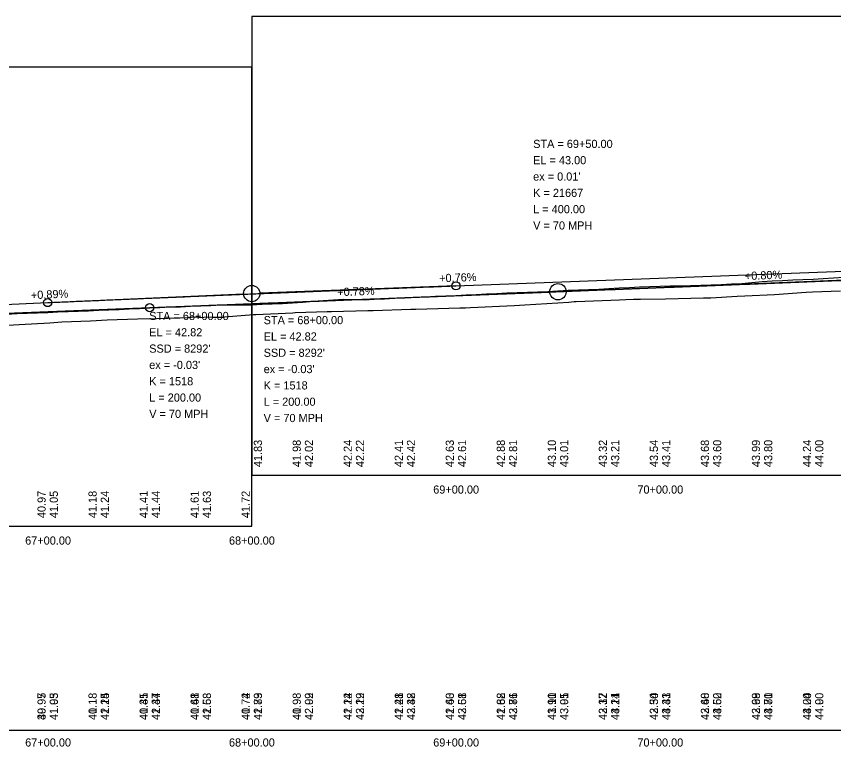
# Model space of a CAD drawing. Extents: x 3880794 to 3915434, y 287517 to 300173.
# Drawn here: x 3887223 to 3887623.4, y 297716.1 to 298074.2 of the extents above; entities that cross this region are included whole.
import ezdxf

# ---------------------------------------------------------------- set-up
doc = ezdxf.new("R2010")
doc.units = 0
for name, color, linetype in [('Level 1', 7, 'Continuous'), ('Level 2', 7, 'Continuous'), ('Level 30', 7, 'Continuous'), ('Level 31', 7, 'Continuous'), ('Level 32', 7, 'Continuous'), ('Level 62', 7, 'Continuous'), ('Level 63', 7, 'Continuous')]:
    doc.layers.add(name, color=color, linetype=linetype)

msp = doc.modelspace()

# ---------------------------------------------------------------- linework, layer by layer
at = {"layer": 'Level 1'}
for p, q in [((3887688.3, 297947.19), (3887492.29, 297939.35)), ((3887288.3, 297931.38), (3887484.3, 297939.03)), ((3886713.3, 297908.91), (3887288.3, 297931.38))]:
    msp.add_line(p, q, dxfattribs=at)
for points in [[(3887521.59, 297935.39), (3887525.37, 297935.54), (3887528.7, 297935.59), (3887541.06, 297935.71), (3887559.54, 297936.12), (3887563.11, 297936.16), (3887576.02, 297936.94), (3887579.85, 297937.17), (3887594.39, 297937.86), (3887609.96, 297938.98), (3887613.02, 297939.16), (3887626.71, 297939.64)], [(3887215.89, 297922.63), (3887224.27, 297923.17), (3887239.4, 297923.99), (3887245.2, 297924.35), (3887259.26, 297924.86), (3887267.48, 297925.36), (3887282.24, 297925.81), (3887291.65, 297925.98), (3887303.06, 297926.43), (3887307.21, 297926.6), (3887308.82, 297926.73), (3887311.81, 297926.88), (3887313.02, 297926.58), (3887314.82, 297926.78), (3887316.18, 297926.81), (3887319.27, 297926.76), (3887323.29, 297926.67), (3887324.28, 297926.76), (3887324.99, 297926.94), (3887339.06, 297927.95), (3887340.27, 297928.01), (3887358.47, 297928.9), (3887359.53, 297928.94), (3887375.16, 297929.54), (3887376.6, 297929.42), (3887376.92, 297929.41), (3887377.28, 297929.41), (3887395.12, 297929.99), (3887397.71, 297930.02), (3887416.2, 297930.69), (3887418.61, 297930.69), (3887440.14, 297931.25), (3887442.95, 297931.29), (3887445.4, 297931.37), (3887466.9, 297932.5), (3887469.46, 297932.63), (3887472.12, 297932.75), (3887493.63, 297934.09), (3887496.17, 297934.32), (3887497.14, 297934.38), (3887518.43, 297935.25), (3887521.59, 297935.39)]]:
    msp.add_lwpolyline(points, dxfattribs=at)
msp.add_circle((3887488.3, 297939.19), 4, dxfattribs=at)
msp.add_spline([(3887288.3, 297931.38), (3887296.3, 297931.69), (3887304.3, 297932), (3887312.3, 297932.31), (3887320.3, 297932.63), (3887328.3, 297932.94), (3887336.3, 297933.25), (3887344.3, 297933.57), (3887352.3, 297933.88), (3887360.3, 297934.2), (3887368.3, 297934.51), (3887376.3, 297934.82), (3887384.3, 297935.14), (3887392.3, 297935.45), (3887400.3, 297935.77), (3887408.3, 297936.08), (3887416.3, 297936.4), (3887424.3, 297936.71), (3887432.3, 297937.03), (3887440.3, 297937.34), (3887448.3, 297937.66), (3887456.3, 297937.97), (3887464.3, 297938.29), (3887472.3, 297938.6), (3887480.3, 297938.92), (3887488.3, 297939.24), (3887496.3, 297939.55), (3887504.3, 297939.87), (3887512.3, 297940.19), (3887520.3, 297940.5), (3887528.3, 297940.82), (3887536.3, 297941.14), (3887544.3, 297941.45), (3887552.3, 297941.77), (3887560.3, 297942.09), (3887568.3, 297942.41), (3887576.3, 297942.73), (3887584.3, 297943.04), (3887592.3, 297943.36), (3887600.3, 297943.68), (3887608.3, 297944), (3887616.3, 297944.32), (3887624.3, 297944.64), (3887632.3, 297944.95), (3887640.3, 297945.27), (3887648.3, 297945.59), (3887656.3, 297945.91), (3887664.3, 297946.23), (3887672.3, 297946.55), (3887680.3, 297946.87), (3887688.3, 297947.19)], degree=3, dxfattribs=at)
at = {"layer": 'Level 2'}
for p, q in [((3887438.3, 297942.07), (3888173.3, 297969.84)), ((3887438.3, 297942.07), (3887342.29, 297938.44)), ((3887238.3, 297933.85), (3887334.3, 297938.11)), ((3886763.3, 297912.78), (3887238.3, 297933.85))]:
    msp.add_line(p, q, dxfattribs=at)
for points in [[(3887538.3, 297941.91), (3887543.3, 297942.1), (3887548.3, 297942.11), (3887553.3, 297942.2), (3887558.3, 297942.37), (3887563.3, 297942.57), (3887568.3, 297942.78), (3887573.3, 297943.02), (3887578.3, 297943.21), (3887583.3, 297943.7), (3887588.3, 297944.12), (3887593.3, 297944.45), (3887598.3, 297944.71), (3887603.3, 297944.97), (3887608.3, 297945.23), (3887613.3, 297945.41), (3887618.3, 297945.67), (3887623.3, 297946), (3887628.3, 297946.33)], [(3887218.3, 297928.22), (3887223.3, 297928.42), (3887228.3, 297928.61), (3887233.3, 297928.83), (3887238.3, 297929.03), (3887243.3, 297929.24), (3887248.3, 297929.44), (3887253.3, 297929.65), (3887258.3, 297929.85), (3887263.3, 297930.07), (3887268.3, 297930.29), (3887273.3, 297930.51), (3887278.3, 297930.72), (3887283.3, 297930.97), (3887288.3, 297931.23), (3887293.3, 297931.49), (3887298.3, 297931.75), (3887303.3, 297931.83), (3887308.3, 297932.04), (3887313.3, 297932.25), (3887318.3, 297932.46), (3887323.3, 297932.67), (3887328.3, 297932.76), (3887333.3, 297932.78), (3887338.3, 297932.81), (3887343.3, 297933), (3887348.3, 297933.23), (3887353.3, 297933.46), (3887358.3, 297933.69), (3887363.3, 297934.1), (3887368.3, 297934.51), (3887373.3, 297934.92), (3887378.3, 297935.19), (3887383.3, 297935.48), (3887388.3, 297935.38), (3887393.3, 297935.14), (3887398.3, 297935.45), (3887403.3, 297935.75), (3887408.3, 297936.03), (3887413.3, 297936.25), (3887418.3, 297936.49), (3887423.3, 297936.73), (3887428.3, 297936.96), (3887433.3, 297937.19), (3887438.3, 297937.35), (3887443.3, 297937.59), (3887448.3, 297937.86), (3887453.3, 297938.13), (3887458.3, 297938.38), (3887463.3, 297938.59), (3887468.3, 297938.79), (3887473.3, 297938.99), (3887478.3, 297939.07), (3887483.3, 297939.32), (3887488.3, 297939.69), (3887493.3, 297939.88), (3887498.3, 297940.04), (3887503.3, 297940.21), (3887508.3, 297940.5), (3887513.3, 297940.81), (3887518.3, 297941.04), (3887523.3, 297941.28), (3887528.3, 297941.52), (3887533.3, 297941.71), (3887538.3, 297941.91)]]:
    msp.add_lwpolyline(points, dxfattribs=at)
for centre, radius in [((3887338.3, 297938.29), 4), ((3887438.3, 297942.07), 2), ((3887238.3, 297933.85), 2)]:
    msp.add_circle(centre, radius, dxfattribs=at)
msp.add_spline([(3887238.3, 297933.85), (3887242.3, 297934.03), (3887246.3, 297934.21), (3887250.3, 297934.38), (3887254.3, 297934.56), (3887258.3, 297934.73), (3887262.3, 297934.91), (3887266.3, 297935.08), (3887270.3, 297935.26), (3887274.3, 297935.43), (3887278.3, 297935.6), (3887282.3, 297935.77), (3887286.3, 297935.95), (3887290.3, 297936.12), (3887294.3, 297936.29), (3887298.3, 297936.46), (3887302.3, 297936.63), (3887306.3, 297936.79), (3887310.3, 297936.96), (3887314.3, 297937.13), (3887318.3, 297937.3), (3887322.3, 297937.47), (3887326.3, 297937.63), (3887330.3, 297937.8), (3887334.3, 297937.96), (3887338.3, 297938.13), (3887342.3, 297938.29), (3887346.3, 297938.45), (3887350.3, 297938.62), (3887354.3, 297938.78), (3887358.3, 297938.94), (3887362.3, 297939.1), (3887366.3, 297939.26), (3887370.3, 297939.42), (3887374.3, 297939.58), (3887378.3, 297939.74), (3887382.3, 297939.9), (3887386.3, 297940.06), (3887390.3, 297940.22), (3887394.3, 297940.37), (3887398.3, 297940.53), (3887402.3, 297940.69), (3887406.3, 297940.84), (3887410.3, 297941), (3887414.3, 297941.15), (3887418.3, 297941.31), (3887422.3, 297941.46), (3887426.3, 297941.61), (3887430.3, 297941.77), (3887434.3, 297941.92), (3887438.3, 297942.07)], degree=3, dxfattribs=at)
at = {"layer": 'Level 31'}
msp.add_circle((3887288.3, 297931.38), 2, dxfattribs=at)
at = {"layer": 'Level 62'}
for points in [[(3887338.3, 297849.19), (3888038.3, 297849.19), (3888038.3, 298074.19), (3887338.3, 298074.19)], [(3887338.3, 297849.19), (3888038.3, 297849.19), (3888038.3, 298074.19), (3887338.3, 298074.19)], [(3886638.3, 297824.19), (3887338.3, 297824.19), (3887338.3, 298049.19), (3886638.3, 298049.19)], [(3886638.3, 297824.19), (3887338.3, 297824.19), (3887338.3, 298049.19), (3886638.3, 298049.19)]]:
    msp.add_lwpolyline(points, close=True, dxfattribs=at)
at = {"layer": 'Level 63'}
msp.add_line((3881538.3, 297724.19), (3896411.35, 297724.19), dxfattribs=at)

# ---------------------------------------------------------------- texts
at = {"layer": 'Level 2'}
for s, rotation, p in [('+0.76%', 2.1635, (3887430.16, 297943.76)), ('+0.89%', 2.5402, (3887230.16, 297935.49))]:
    msp.add_text(s, height=4, rotation=rotation, dxfattribs=at).set_placement(p)
for s, p in [('STA = 68+00.00', (3887288.04, 297925.29)), ('STA = 68+00.00', (3887344.11, 297923.26)), ('EL = 42.82', (3887288.04, 297917.29)), ('EL = 42.82', (3887344.11, 297915.26)), ("SSD = 8292'", (3887288.04, 297909.29)), ("SSD = 8292'", (3887344.11, 297907.26)), ("ex = -0.03'", (3887288.04, 297901.29)), ("ex = -0.03'", (3887344.11, 297899.26)), ('K = 1518', (3887288.04, 297893.29)), ('K = 1518', (3887344.11, 297891.26)), ('L = 200.00', (3887288.04, 297885.29)), ('L = 200.00', (3887344.11, 297883.26)), ('V = 70 MPH', (3887288.04, 297877.29)), ('V = 70 MPH', (3887344.11, 297875.26))]:
    msp.add_text(s, height=4, dxfattribs=at).set_placement(p)
at = {"layer": 'Level 30'}
for s, p in [('69+00.00', (3887427.18, 297840.19)), ('69+00.00', (3887427.18, 297840.19)), ('70+00.00', (3887527.21, 297840.19)), ('70+00.00', (3887527.21, 297840.19)), ('67+00.00', (3887227.27, 297815.19)), ('67+00.00', (3887227.27, 297815.19)), ('68+00.00', (3887327.12, 297815.19)), ('68+00.00', (3887327.12, 297815.19)), ('67+00.00', (3887227.27, 297716.19)), ('67+00.00', (3887227.27, 297716.19)), ('68+00.00', (3887327.12, 297716.19)), ('68+00.00', (3887327.12, 297716.19)), ('69+00.00', (3887427.18, 297716.19)), ('69+00.00', (3887427.18, 297716.19)), ('70+00.00', (3887527.21, 297716.19)), ('70+00.00', (3887527.21, 297716.19))]:
    msp.add_text(s, height=4, dxfattribs=at).set_placement(p)
at = {"layer": 'Level 31'}
for s, p in [('STA = 69+50.00', (3887476.14, 298009.66)), ('EL = 43.00', (3887476.14, 298001.66)), ("ex = 0.01'", (3887476.14, 297993.66)), ('K = 21667', (3887476.14, 297985.66)), ('L = 400.00', (3887476.14, 297977.66)), ('V = 70 MPH', (3887476.14, 297969.66))]:
    msp.add_text(s, height=4, dxfattribs=at).set_placement(p)
for s, rotation, p in [('+0.80%', 2.2906, (3887579.93, 297944.86)), ('+0.78%', 2.2378, (3887380.24, 297936.97)), ('41.83', 90, (3887343.3, 297853.19)), ('42.02', 90, (3887368.3, 297853.19)), ('42.22', 90, (3887393.3, 297853.19)), ('42.42', 90, (3887418.3, 297853.19)), ('42.61', 90, (3887443.3, 297853.19)), ('42.81', 90, (3887468.3, 297853.19)), ('43.01', 90, (3887493.3, 297853.19)), ('43.21', 90, (3887518.3, 297853.19)), ('43.41', 90, (3887543.3, 297853.19)), ('43.60', 90, (3887568.3, 297853.19)), ('43.80', 90, (3887593.3, 297853.19)), ('44.00', 90, (3887618.3, 297853.19)), ('41.05', 90, (3887243.3, 297828.19)), ('41.24', 90, (3887268.3, 297828.19)), ('41.44', 90, (3887293.3, 297828.19)), ('41.63', 90, (3887318.3, 297828.19)), ('39.95', 90, (3887237.3, 297729.19)), ('41.05', 90, (3887243.3, 297729.19)), ('40.18', 90, (3887262.3, 297729.19)), ('41.24', 90, (3887268.3, 297729.19)), ('40.35', 90, (3887287.3, 297729.19)), ('41.44', 90, (3887293.3, 297729.19)), ('40.48', 90, (3887312.3, 297729.19)), ('41.63', 90, (3887318.3, 297729.19)), ('40.74', 90, (3887337.3, 297729.19)), ('41.83', 90, (3887343.3, 297729.19)), ('40.98', 90, (3887362.3, 297729.19)), ('42.02', 90, (3887368.3, 297729.19)), ('41.12', 90, (3887387.3, 297729.19)), ('42.22', 90, (3887393.3, 297729.19)), ('41.28', 90, (3887412.3, 297729.19)), ('42.42', 90, (3887418.3, 297729.19)), ('41.40', 90, (3887437.3, 297729.19)), ('42.61', 90, (3887443.3, 297729.19)), ('41.62', 90, (3887462.3, 297729.19)), ('42.81', 90, (3887468.3, 297729.19)), ('41.91', 90, (3887487.3, 297729.19)), ('43.01', 90, (3887493.3, 297729.19)), ('42.17', 90, (3887512.3, 297729.19)), ('43.21', 90, (3887518.3, 297729.19)), ('42.30', 90, (3887537.3, 297729.19)), ('43.41', 90, (3887543.3, 297729.19)), ('42.40', 90, (3887562.3, 297729.19)), ('43.60', 90, (3887568.3, 297729.19)), ('42.68', 90, (3887587.3, 297729.19)), ('43.80', 90, (3887593.3, 297729.19)), ('43.00', 90, (3887612.3, 297729.19)), ('44.00', 90, (3887618.3, 297729.19))]:
    msp.add_text(s, height=4, rotation=rotation, dxfattribs=at).set_placement(p)
at = {"layer": 'Level 32'}
for s, p in [('41.98', (3887362.3, 297853.19)), ('42.24', (3887387.3, 297853.19)), ('42.41', (3887412.3, 297853.19)), ('42.63', (3887437.3, 297853.19)), ('42.88', (3887462.3, 297853.19)), ('43.10', (3887487.3, 297853.19)), ('43.32', (3887512.3, 297853.19)), ('43.54', (3887537.3, 297853.19)), ('43.68', (3887562.3, 297853.19)), ('43.99', (3887587.3, 297853.19)), ('44.24', (3887612.3, 297853.19)), ('40.97', (3887237.3, 297828.19)), ('41.18', (3887262.3, 297828.19)), ('41.41', (3887287.3, 297828.19)), ('41.61', (3887312.3, 297828.19)), ('41.72', (3887337.3, 297828.19)), ('40.97', (3887237.3, 297729.19)), ('41.93', (3887243.3, 297729.19)), ('41.18', (3887262.3, 297729.19)), ('42.15', (3887268.3, 297729.19)), ('41.41', (3887287.3, 297729.19)), ('42.37', (3887293.3, 297729.19)), ('41.61', (3887312.3, 297729.19)), ('42.58', (3887318.3, 297729.19)), ('41.72', (3887337.3, 297729.19)), ('42.79', (3887343.3, 297729.19)), ('41.98', (3887362.3, 297729.19)), ('42.99', (3887368.3, 297729.19)), ('42.24', (3887387.3, 297729.19)), ('43.19', (3887393.3, 297729.19)), ('42.41', (3887412.3, 297729.19)), ('43.38', (3887418.3, 297729.19)), ('42.63', (3887437.3, 297729.19)), ('43.58', (3887443.3, 297729.19)), ('42.88', (3887462.3, 297729.19)), ('43.76', (3887468.3, 297729.19)), ('43.10', (3887487.3, 297729.19)), ('43.95', (3887493.3, 297729.19)), ('43.32', (3887512.3, 297729.19)), ('44.14', (3887518.3, 297729.19)), ('43.54', (3887537.3, 297729.19)), ('44.33', (3887543.3, 297729.19)), ('43.68', (3887562.3, 297729.19)), ('44.52', (3887568.3, 297729.19)), ('43.99', (3887587.3, 297729.19)), ('44.71', (3887593.3, 297729.19)), ('44.24', (3887612.3, 297729.19)), ('44.90', (3887618.3, 297729.19))]:
    msp.add_text(s, height=4, rotation=90, dxfattribs=at).set_placement(p)

doc.saveas('drawing.dxf')
